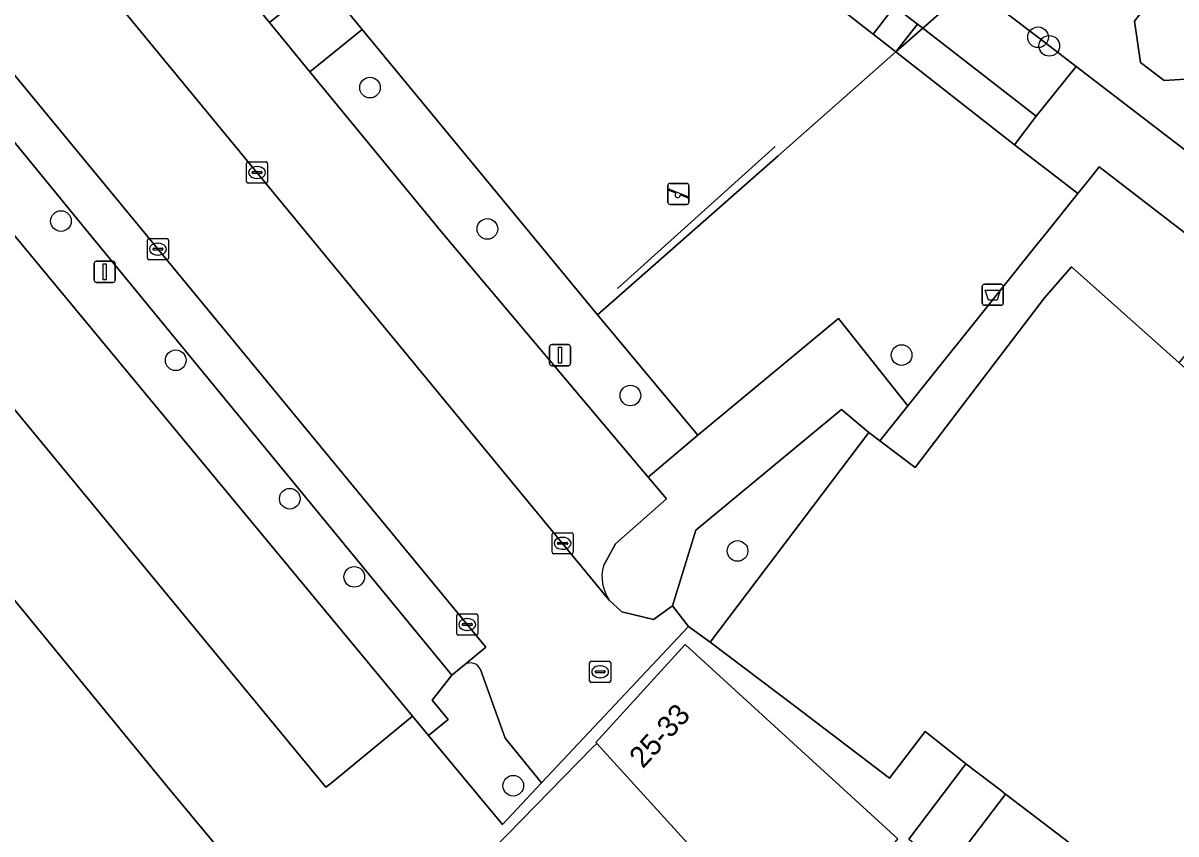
# Model space of a CAD drawing. Extents: x 160663 to 161506, y 382245 to 383291.
# Drawn here: x 160951.6 to 161006.2, y 382971.5 to 383010 of the extents above; entities that cross this region are included whole.
import ezdxf

# ---------------------------------------------------------------- set-up
doc = ezdxf.new("R2010")
doc.units = 0
for name, color, linetype in [('IMGEO_Afvalbak', 7, 'Continuous'), ('IMGEO_Boom', 7, 'Continuous'), ('IMGEO_Erf', 7, 'Continuous'), ('IMGEO_Groenvoorziening', 7, 'Continuous'), ('IMGEO_Hek', 7, 'Continuous'), ('IMGEO_Kolk', 7, 'Continuous'), ('IMGEO_Lichtmast', 7, 'Continuous'), ('IMGEO_Pand', 7, 'Continuous'), ('IMGEO_Pand_nummerreeks', 7, 'Continuous'), ('IMGEO_Parkeervlak_open', 7, 'Continuous'), ('IMGEO_Rijbaan_lokaal_open', 7, 'Continuous'), ('IMGEO_Rioolput', 7, 'Continuous'), ('IMGEO_Speelvoorziening', 7, 'Continuous'), ('IMGEO_Voetpad_halfverhard', 7, 'Continuous'), ('IMGEO_Voetpad_open', 7, 'Continuous')]:
    doc.layers.add(name, color=color, linetype=linetype)

msp = doc.modelspace()

# ---------------------------------------------------------------- linework, layer by layer
at = {"layer": 'IMGEO_Afvalbak'}
for p, q in [((160997.055, 382996.679), (160997.055, 382997.479)), ((160997.055, 382997.479), (160997.055, 382996.679)), ((160997.155, 382997.579), (160997.945, 382997.579)), ((160997.945, 382997.579), (160997.155, 382997.579)), ((160998.045, 382997.479), (160998.045, 382996.679)), ((160998.045, 382996.679), (160998.045, 382997.479)), ((160997.945, 382996.579), (160997.155, 382996.579)), ((160997.155, 382996.579), (160997.945, 382996.579))]:
    msp.add_line(p, q, dxfattribs=at)
msp.add_lwpolyline([(160997.198, 382997.293), (160997.902, 382997.293), (160997.753, 382996.823), (160997.347, 382996.823), (160997.198, 382997.293)], dxfattribs=at)
for centre, start, end in [((160997.155, 382997.479), 90, 180), ((160997.155, 382997.479), 90, 180), ((160997.945, 382997.479), 0, 90), ((160997.945, 382997.479), 360, 90), ((160997.155, 382996.679), 180, 270), ((160997.155, 382996.679), 180, 270), ((160997.945, 382996.679), 270, 0), ((160997.945, 382996.679), 270, 0)]:
    msp.add_arc(centre, 0.1, start, end, dxfattribs=at)
at = {"layer": 'IMGEO_Boom'}
for centre in [(160999.696, 383009.28), (161000.229, 383008.871), (160968.033, 383006.893), (160953.387, 383000.571), (160973.596, 383000.198), (160958.826, 382993.974), (160993.229, 382994.221), (160980.376, 382992.305), (160964.233, 382987.416), (160985.453, 382984.939), (160967.287, 382983.713), (160974.824, 382973.818)]:
    msp.add_circle(centre, 0.489, dxfattribs=at)
at = {"layer": 'IMGEO_Erf'}
for points in [[(160996.515, 383011.718), (161000, 383009.047), (161001.496, 383007.901), (161011.804, 383000), (161024.693, 382990.287), (161032.566, 383000), (161032.638, 383000.108), (161033.349, 383000.985), (161035.309, 383003.404), (161034.299, 383004.235), (161034.173, 383006.162), (161035.066, 383007.264), (161033.307, 383008.711), (161032.628, 383007.886), (161028.208, 383011.521)], [(160936.91, 383000), (160958.423, 382973.784), (160961.617, 382969.937)], [(160993.565, 382971.284), (160996.082, 382974.605), (160996.272, 382974.854), (160996.094, 382974.99), (160994.341, 382976.392), (160992.662, 382974.178), (160988.149, 382977.597), (160984.163, 382980.616), (160983.135, 382981.366), (160976.17, 382973.953), (160974.309, 382971.972), (160970.812, 382976.19), (160970.046, 382977.114), (160966.186, 382973.937), (160965.948, 382973.741), (160944.278, 383000)], [(160973.196, 382970.113), (160978.583, 382975.62), (160978.78, 382975.821), (160978.741, 382975.864), (160982.974, 382980.502), (160993.051, 382971.304)], [(161001.199, 382971.092), (161000, 382972.012), (160998.15, 382973.423), (160995.446, 382969.858)]]:
    msp.add_lwpolyline(points, dxfattribs=at)
for points in [[(161004.266, 383010.049), (161005.355, 383011.463), (161005.675, 383011.484), (161007.123, 383011.574), (161008.38, 383010.504), (161008.62, 383008.85), (161007.455, 383007.339), (161005.669, 383007.226), (161004.551, 383008.078)], [(161000, 382996.936), (161001.288, 382998.396), (161006.384, 382993.846), (161009.678, 382997.924), (161008.031, 382998.962), (161002.601, 383003.14), (161002.198, 383002.638), (161001.583, 383001.871), (161000.083, 383000), (161000, 382999.896), (160999.531, 382999.311), (160998.088, 382997.51), (160993.52, 382991.81), (160992.195, 382990.157), (160993.87, 382988.888)]]:
    msp.add_lwpolyline(points, close=True, dxfattribs=at)
at = {"layer": 'IMGEO_Groenvoorziening'}
for points in [[(160965.611, 383031.867), (160992.9, 383010.739), (160993.983, 383009.901), (160994.233, 383009.708), (160996.515, 383011.718), (160973.741, 383029.173), (160973.09, 383029.971), (160971.555, 383028.72), (160969.249, 383031.55), (160969.738, 383031.948), (160966.352, 383035.958)], [(160972.508, 382979.547), (160972.18, 382979.276), (160971.917, 382979.059), (160970.973, 382977.877), (160971.736, 382976.951), (160970.812, 382976.19), (160974.309, 382971.972), (160976.17, 382973.953), (160974.444, 382976.07)], [(160974.444, 382976.07), (160973.267, 382979.32)]]:
    msp.add_lwpolyline(points, dxfattribs=at)
for points in [[(160991.875, 383009.425), (160973.235, 383023.964), (160962.993, 383015.315), (160965.743, 383011.982), (160967.663, 383009.654), (160975.628, 383000), (160978.82, 382996.131), (160987.376, 383003.668), (160992.955, 383008.582)], [(161001.496, 383007.901), (161000, 383009.047), (160996.515, 383011.718), (160994.233, 383009.708), (160999.613, 383005.542), (161000, 383006.027)], [(160975.628, 383000), (160967.663, 383009.654), (160965.188, 383007.644), (160971.467, 383000), (160981.225, 382988.433), (160983.579, 382990.419), (160978.82, 382996.131)], [(160999.531, 382999.311), (161000, 382999.896), (161000.083, 383000), (161001.583, 383001.871), (161000.396, 383002.789), (161000, 383003.096), (160998.586, 383004.19), (160992.955, 383008.582), (160987.376, 383003.668), (160978.82, 382996.131), (160983.579, 382990.419), (160990.231, 382995.961), (160993.52, 382991.81), (160998.088, 382997.51)], [(160984.163, 382980.616), (160991.683, 382990.545), (160990.38, 382991.644), (160983.481, 382985.923), (160982.365, 382982.335), (160983.135, 382981.366)]]:
    msp.add_lwpolyline(points, close=True, dxfattribs=at)
msp.add_arc((160972.794, 382979.12), 0.514, 22.9356, 123.7629, dxfattribs=at)
at = {"layer": 'IMGEO_Hek'}
for points in [[(160951.771, 383023.978), (160963.274, 383009.974), (160965.743, 383011.982), (160967.663, 383009.654), (160978.82, 382996.131)], [(160994.233, 383009.708), (160996.515, 383011.718)], [(160992.955, 383008.582), (160994.233, 383009.708)], [(160979.758, 382997.374), (160987.235, 383004.108)]]:
    msp.add_lwpolyline(points, dxfattribs=at)
at = {"layer": 'IMGEO_Kolk'}
for p, q in [((160962.18, 383002.445), (160962.18, 383003.297)), ((160962.255, 383003.371), (160963.107, 383003.371)), ((160963.181, 383003.297), (160963.181, 383002.445)), ((160962.439, 383002.865), (160962.439, 383002.877)), ((160962.877, 383002.828), (160962.479, 383002.828)), ((160962.482, 383002.914), (160962.88, 383002.914)), ((160962.668, 383003.151), (160962.693, 383003.151)), ((160962.923, 383002.877), (160962.923, 383002.865)), ((160963.107, 383002.371), (160962.255, 383002.371)), ((160962.691, 383002.591), (160962.666, 383002.591)), ((160957.481, 382998.814), (160957.481, 382999.666)), ((160957.556, 382999.74), (160958.408, 382999.74)), ((160957.969, 382999.52), (160957.994, 382999.52)), ((160958.482, 382999.666), (160958.482, 382998.814)), ((160957.74, 382999.234), (160957.74, 382999.246)), ((160958.178, 382999.197), (160957.78, 382999.197)), ((160957.783, 382999.283), (160958.181, 382999.283)), ((160957.992, 382998.96), (160957.967, 382998.96)), ((160958.224, 382999.246), (160958.224, 382999.234)), ((160958.408, 382998.74), (160957.556, 382998.74)), ((160976.662, 382984.876), (160976.662, 382985.728)), ((160976.737, 382985.802), (160977.589, 382985.802)), ((160977.663, 382985.728), (160977.663, 382984.876)), ((160976.921, 382985.296), (160976.921, 382985.308)), ((160977.359, 382985.259), (160976.961, 382985.259)), ((160976.964, 382985.345), (160977.362, 382985.345)), ((160977.15, 382985.582), (160977.175, 382985.582)), ((160977.405, 382985.308), (160977.405, 382985.296)), ((160977.589, 382984.802), (160976.737, 382984.802)), ((160977.173, 382985.022), (160977.148, 382985.022)), ((160972.142, 382981.03), (160972.142, 382981.882)), ((160972.217, 382981.956), (160973.069, 382981.956)), ((160973.143, 382981.882), (160973.143, 382981.03)), ((160972.401, 382981.45), (160972.401, 382981.462)), ((160972.839, 382981.413), (160972.441, 382981.413)), ((160972.444, 382981.499), (160972.842, 382981.499)), ((160972.63, 382981.736), (160972.655, 382981.736)), ((160972.885, 382981.462), (160972.885, 382981.45)), ((160973.069, 382980.956), (160972.217, 382980.956)), ((160972.653, 382981.176), (160972.628, 382981.176))]:
    msp.add_line(p, q, dxfattribs=at)
for points in [[(160962.18, 383002.445), (160962.18, 383003.297)], [(160962.255, 383003.371), (160963.107, 383003.371)], [(160963.181, 383003.297), (160963.181, 383002.445)], [(160963.107, 383002.371), (160962.255, 383002.371)], [(160957.481, 382998.814), (160957.481, 382999.666)], [(160957.556, 382999.74), (160958.408, 382999.74)], [(160958.482, 382999.666), (160958.482, 382998.814)], [(160958.408, 382998.74), (160957.556, 382998.74)], [(160976.662, 382984.876), (160976.662, 382985.728)], [(160976.737, 382985.802), (160977.589, 382985.802)], [(160977.663, 382985.728), (160977.663, 382984.876)], [(160977.589, 382984.802), (160976.737, 382984.802)], [(160972.142, 382981.03), (160972.142, 382981.882)], [(160972.217, 382981.956), (160973.069, 382981.956)], [(160973.143, 382981.882), (160973.143, 382981.03)], [(160973.069, 382980.956), (160972.217, 382980.956)]]:
    msp.add_lwpolyline(points, dxfattribs=at)
for centre, radius, start, end in [((160962.257, 383003.295), 0.0765, 91.552, 178.448), ((160962.257, 383003.295), 0.0765, 91.552, 178.448), ((160963.105, 383003.295), 0.0765, 1.552, 88.448), ((160963.105, 383003.295), 0.0765, 1.552, 88.448), ((160962.479, 383002.874), 0.0403, 85.8775, 175.7526), ((160962.476, 383002.864), 0.0366, 178.938, 274.7102), ((160962.88, 383002.871), 0.043, 264.8664, 352.4533), ((160962.884, 383002.876), 0.0386, 1.7309, 96.639), ((160962.257, 383002.447), 0.0765, 181.552, 268.448), ((160962.257, 383002.447), 0.0765, 181.552, 268.448), ((160963.105, 383002.447), 0.0765, 271.552, 358.448), ((160963.105, 383002.447), 0.0765, 271.552, 358.448), ((160957.558, 382999.664), 0.0765, 91.552, 178.448), ((160957.558, 382999.664), 0.0765, 91.552, 178.448), ((160958.406, 382999.664), 0.0765, 1.552, 88.448), ((160958.406, 382999.664), 0.0765, 1.552, 88.448), ((160957.558, 382998.816), 0.0765, 181.552, 268.448), ((160957.558, 382998.816), 0.0765, 181.552, 268.448), ((160957.78, 382999.243), 0.0403, 85.8775, 175.7526), ((160957.777, 382999.233), 0.0366, 178.938, 274.7102), ((160958.181, 382999.24), 0.043, 264.8664, 352.4533), ((160958.185, 382999.245), 0.0386, 1.7309, 96.639), ((160958.406, 382998.816), 0.0765, 271.552, 358.448), ((160958.406, 382998.816), 0.0765, 271.552, 358.448), ((160976.739, 382985.726), 0.0765, 91.552, 178.448), ((160976.739, 382985.726), 0.0765, 91.552, 178.448), ((160977.587, 382985.726), 0.0765, 1.552, 88.448), ((160977.587, 382985.726), 0.0765, 1.552, 88.448), ((160976.961, 382985.305), 0.0403, 85.8775, 175.7526), ((160976.958, 382985.295), 0.0366, 178.938, 274.7102), ((160977.362, 382985.302), 0.043, 264.8664, 352.4533), ((160977.366, 382985.307), 0.0386, 1.7309, 96.639), ((160976.739, 382984.878), 0.0765, 181.552, 268.448), ((160976.739, 382984.878), 0.0765, 181.552, 268.448), ((160977.587, 382984.878), 0.0765, 271.552, 358.448), ((160977.587, 382984.878), 0.0765, 271.552, 358.448), ((160972.219, 382981.88), 0.0765, 91.552, 178.448), ((160972.219, 382981.88), 0.0765, 91.552, 178.448), ((160973.067, 382981.88), 0.0765, 1.552, 88.448), ((160973.067, 382981.88), 0.0765, 1.552, 88.448), ((160972.441, 382981.459), 0.0403, 85.8775, 175.7526), ((160972.438, 382981.449), 0.0366, 178.938, 274.7102), ((160972.842, 382981.456), 0.043, 264.8664, 352.4533), ((160972.846, 382981.461), 0.0386, 1.7309, 96.639), ((160972.219, 382981.032), 0.0765, 181.552, 268.448), ((160972.219, 382981.032), 0.0765, 181.552, 268.448), ((160973.067, 382981.032), 0.0765, 271.552, 358.448), ((160973.067, 382981.032), 0.0765, 271.552, 358.448)]:
    msp.add_arc(centre, radius, start, end, dxfattribs=at)
for centre, major_axis, ratio, start_param, end_param in [((160962.667, 383002.871), (-0.387, 0.002), 0.722429, 4.712389, 7.853982), ((160962.692, 383002.871), (-0.39, 0.002), 0.717154, 1.570796, 4.712389), ((160957.968, 382999.24), (-0.387, 0.002), 0.722429, 4.712389, 7.853982), ((160957.993, 382999.24), (-0.39, 0.002), 0.717154, 1.570796, 4.712389), ((160977.149, 382985.302), (-0.387, 0.002), 0.722429, 4.712389, 7.853982), ((160977.174, 382985.302), (-0.39, 0.002), 0.717154, 1.570796, 4.712389), ((160972.629, 382981.456), (-0.387, 0.002), 0.722429, 4.712389, 7.853982), ((160972.654, 382981.456), (-0.39, 0.002), 0.717154, 1.570796, 4.712389)]:
    msp.add_ellipse(centre, major_axis=major_axis, ratio=ratio, start_param=start_param, end_param=end_param, dxfattribs=at)
at = {"layer": 'IMGEO_Lichtmast'}
for p, q in [((160954.961, 382997.766), (160954.961, 382998.566)), ((160954.961, 382998.566), (160954.961, 382997.766)), ((160955.061, 382998.666), (160955.851, 382998.666)), ((160955.851, 382998.666), (160955.061, 382998.666)), ((160955.951, 382998.566), (160955.951, 382997.766)), ((160955.951, 382997.766), (160955.951, 382998.566)), ((160955.851, 382997.666), (160955.061, 382997.666)), ((160955.061, 382997.666), (160955.851, 382997.666)), ((160976.546, 382993.815), (160976.546, 382994.615)), ((160976.546, 382994.615), (160976.546, 382993.815)), ((160976.646, 382994.715), (160977.436, 382994.715)), ((160977.436, 382994.715), (160976.646, 382994.715)), ((160977.536, 382994.615), (160977.536, 382993.815)), ((160977.536, 382993.815), (160977.536, 382994.615)), ((160977.436, 382993.715), (160976.646, 382993.715)), ((160976.646, 382993.715), (160977.436, 382993.715))]:
    msp.add_line(p, q, dxfattribs=at)
for points in [[(160955.381, 382998.541), (160955.531, 382998.541), (160955.531, 382997.791), (160955.381, 382997.791), (160955.381, 382998.541)], [(160976.966, 382994.59), (160977.116, 382994.59), (160977.116, 382993.84), (160976.966, 382993.84), (160976.966, 382994.59)]]:
    msp.add_lwpolyline(points, dxfattribs=at)
for centre, start, end in [((160955.061, 382998.566), 90, 180), ((160955.061, 382998.566), 90, 180), ((160955.851, 382998.566), 0, 90), ((160955.851, 382998.566), 360, 90), ((160955.061, 382997.766), 180, 270), ((160955.061, 382997.766), 180, 270), ((160955.851, 382997.766), 270, 0), ((160955.851, 382997.766), 270, 0), ((160976.646, 382994.615), 90, 180), ((160976.646, 382994.615), 90, 180), ((160977.436, 382994.615), 0, 90), ((160977.436, 382994.615), 360, 90), ((160976.646, 382993.815), 180, 270), ((160976.646, 382993.815), 180, 270), ((160977.436, 382993.815), 270, 0), ((160977.436, 382993.815), 270, 0)]:
    msp.add_arc(centre, 0.1, start, end, dxfattribs=at)
at = {"layer": 'IMGEO_Pand'}
for points in [[(160970.046, 382977.114), (160951.094, 383000), (160937.187, 383016.894), (160933.327, 383013.717), (160933.107, 383013.536), (160944.278, 383000), (160965.948, 382973.741), (160966.186, 382973.937)], [(160936.91, 383000), (160925.377, 383014.054), (160925.308, 383014.138), (160917.332, 383007.56), (160917.629, 383007.213), (160923.54, 383000), (160953.589, 382963.329), (160961.617, 382969.937), (160958.423, 382973.784)], [(161004.266, 383010.049), (161004.551, 383008.078), (161005.669, 383007.226), (161007.455, 383007.339), (161008.62, 383008.85), (161008.38, 383010.504), (161007.123, 383011.574), (161005.675, 383011.484), (161005.355, 383011.463)], [(161021.889, 382983.539), (161021.424, 382982.963), (161020.229, 382981.484), (161010.392, 382990.267), (161006.384, 382993.846), (161001.288, 382998.396), (161000, 382996.936), (160993.87, 382988.888), (160992.195, 382990.157), (160991.683, 382990.545), (160984.163, 382980.616), (160988.149, 382977.597), (160992.662, 382974.178), (160994.341, 382976.392), (160996.094, 382974.99), (160996.272, 382974.854), (160997.96, 382973.567), (160998.081, 382973.475), (160998.15, 382973.423), (161000, 382972.012), (161001.199, 382971.092), (161002.915, 382969.775), (161015.758, 382959.65), (161029.997, 382977.303)], [(160982.974, 382980.502), (160978.741, 382975.864), (160978.78, 382975.821), (160988.34, 382965.314), (160993.051, 382971.304)], [(160978.78, 382975.821), (160978.583, 382975.62), (160973.196, 382970.113), (160978.517, 382965.213), (160977.888, 382964.488), (160983.601, 382959.296), (160983.622, 382959.281), (160984.019, 382959.789), (160988.236, 382965.181), (160988.34, 382965.314)], [(160998.15, 382973.423), (160998.081, 382973.475), (160997.96, 382973.567), (160996.272, 382974.854), (160996.082, 382974.605), (160993.565, 382971.284), (160995.111, 382970.112), (160995.377, 382969.91), (160995.446, 382969.858)]]:
    msp.add_lwpolyline(points, close=True, dxfattribs=at)
at = {"layer": 'IMGEO_Parkeervlak_open'}
for points in [[(160965.188, 383007.644), (160963.274, 383009.974), (160951.771, 383023.978), (160947.904, 383020.802), (160965.045, 383000), (160979.376, 382982.615)], [(160938.803, 383018.726), (160941.068, 383016.598), (160942.148, 383015.356), (160954.712, 383000), (160965.713, 382986.582), (160971.917, 382979.059), (160972.18, 382979.276), (160972.508, 382979.547), (160973.527, 382980.386), (160957.356, 383000), (160944.076, 383016.107)], [(160979.095, 382984.232), (160979.664, 382985.281), (160982.084, 382987.414), (160981.225, 382988.433), (160971.467, 383000), (160965.188, 383007.644)]]:
    msp.add_lwpolyline(points, dxfattribs=at)
msp.add_arc((160980.966, 382983.724), 1.939, 164.8162, 214.9004, dxfattribs=at)
at = {"layer": 'IMGEO_Rijbaan_lokaal_open'}
for points in [[(160944.793, 383020.424), (160941.074, 383023.981), (160920.302, 383043.863), (160917.937, 383041.481), (160918.109, 383041.314), (160931.492, 383028.374), (160941.045, 383019.344), (160942.976, 383017.415), (160944.076, 383016.107), (160957.356, 383000), (160973.527, 382980.386), (160972.508, 382979.547)], [(160973.267, 382979.32), (160974.444, 382976.07), (160976.17, 382973.953), (160983.135, 382981.366), (160982.365, 382982.335), (160981.47, 382981.695), (160979.968, 382982.054), (160979.376, 382982.615), (160965.045, 383000), (160947.904, 383020.802)]]:
    msp.add_lwpolyline(points, dxfattribs=at)
msp.add_arc((160972.794, 382979.12), 0.514, 22.9356, 123.7629, dxfattribs=at)
at = {"layer": 'IMGEO_Rioolput'}
for p, q in [((160978.517, 382979.715), (160979.369, 382979.715)), ((160978.442, 382978.789), (160978.442, 382979.641)), ((160978.701, 382979.209), (160978.701, 382979.221)), ((160979.139, 382979.172), (160978.741, 382979.172)), ((160978.744, 382979.258), (160979.142, 382979.258)), ((160978.93, 382979.495), (160978.955, 382979.495)), ((160979.185, 382979.221), (160979.185, 382979.209)), ((160979.443, 382979.641), (160979.443, 382978.789)), ((160979.369, 382978.715), (160978.517, 382978.715)), ((160978.953, 382978.935), (160978.928, 382978.935))]:
    msp.add_line(p, q, dxfattribs=at)
for points in [[(160978.517, 382979.715), (160979.369, 382979.715)], [(160978.442, 382978.789), (160978.442, 382979.641)], [(160979.443, 382979.641), (160979.443, 382978.789)], [(160979.369, 382978.715), (160978.517, 382978.715)]]:
    msp.add_lwpolyline(points, dxfattribs=at)
for centre, radius, start, end in [((160978.519, 382979.639), 0.0765, 91.552, 178.448), ((160978.519, 382979.639), 0.0765, 91.552, 178.448), ((160979.367, 382979.639), 0.0765, 1.552, 88.448), ((160979.367, 382979.639), 0.0765, 1.552, 88.448), ((160978.741, 382979.218), 0.0403, 85.8775, 175.7526), ((160978.738, 382979.208), 0.0366, 178.938, 274.7102), ((160979.142, 382979.215), 0.043, 264.8664, 352.4533), ((160979.146, 382979.22), 0.0386, 1.7309, 96.639), ((160978.519, 382978.791), 0.0765, 181.552, 268.448), ((160978.519, 382978.791), 0.0765, 181.552, 268.448), ((160979.367, 382978.791), 0.0765, 271.552, 358.448), ((160979.367, 382978.791), 0.0765, 271.552, 358.448)]:
    msp.add_arc(centre, radius, start, end, dxfattribs=at)
for centre, major_axis, ratio, start_param, end_param in [((160978.929, 382979.215), (-0.387, 0.002), 0.722429, 4.712389, 7.853982), ((160978.954, 382979.215), (-0.39, 0.002), 0.717154, 1.570796, 4.712389)]:
    msp.add_ellipse(centre, major_axis=major_axis, ratio=ratio, start_param=start_param, end_param=end_param, dxfattribs=at)
at = {"layer": 'IMGEO_Speelvoorziening'}
for p, q in [((160982.154, 383001.457), (160982.154, 383002.257)), ((160982.154, 383002.257), (160982.154, 383001.457)), ((160982.254, 383002.357), (160983.044, 383002.357)), ((160983.044, 383002.357), (160982.254, 383002.357)), ((160983.144, 383002.257), (160983.144, 383001.457)), ((160983.144, 383001.457), (160983.144, 383002.257)), ((160982.537, 383001.885), (160982.198, 383002.022)), ((160982.223, 383002.082), (160983.099, 383001.729)), ((160983.075, 383001.669), (160982.735, 383001.806)), ((160983.044, 383001.357), (160982.254, 383001.357)), ((160982.254, 383001.357), (160983.044, 383001.357))]:
    msp.add_line(p, q, dxfattribs=at)
for centre, radius, start, end in [((160982.254, 383002.257), 0.1, 90, 180), ((160982.254, 383002.257), 0.1, 90, 180), ((160982.211, 383002.052), 0.0327, 68.078, 248.078), ((160983.044, 383002.257), 0.1, 0, 90), ((160983.044, 383002.257), 0.1, 360, 90), ((160982.616, 383001.795), 0.12, 130.9928, 5.1632), ((160983.087, 383001.699), 0.0327, 248.078, 68.078), ((160982.254, 383001.457), 0.1, 180, 270), ((160982.254, 383001.457), 0.1, 180, 270), ((160983.044, 383001.457), 0.1, 270, 0), ((160983.044, 383001.457), 0.1, 270, 0)]:
    msp.add_arc(centre, radius, start, end, dxfattribs=at)
at = {"layer": 'IMGEO_Voetpad_halfverhard'}
msp.add_lwpolyline([(160955.126, 383026.948), (160954.085, 383026.085), (160957.797, 383021.6), (160962.413, 383025.421), (160966.287, 383028.692), (160966.717, 383029.048), (160973.235, 383023.964), (160991.875, 383009.425), (160992.9, 383010.739), (160965.611, 383031.867), (160958.925, 383026.141), (160954.207, 383028.3), (160954.088, 383028.201)], close=True, dxfattribs=at)
at = {"layer": 'IMGEO_Voetpad_open'}
for points in [[(160917.623, 383041.165), (160916.299, 383039.832), (160916.51, 383039.63), (160928.616, 383028.044), (160931.868, 383024.973), (160937.287, 383019.841), (160935.954, 383018.87), (160937.187, 383016.894), (160951.094, 383000), (160970.046, 382977.114), (160970.812, 382976.19), (160971.736, 382976.951), (160970.973, 382977.877), (160971.917, 382979.059), (160965.713, 382986.582), (160954.712, 383000), (160942.148, 383015.356), (160941.068, 383016.598), (160938.803, 383018.726)], [(160983.481, 382985.923), (160990.38, 382991.644), (160991.683, 382990.545), (160992.195, 382990.157), (160993.52, 382991.81), (160990.231, 382995.961), (160983.579, 382990.419), (160981.225, 382988.433), (160982.084, 382987.414), (160979.664, 382985.281), (160979.095, 382984.232)], [(160979.376, 382982.615), (160979.968, 382982.054), (160981.47, 382981.695), (160982.365, 382982.335), (160983.481, 382985.923)]]:
    msp.add_lwpolyline(points, dxfattribs=at)
for points in [[(160965.188, 383007.644), (160967.663, 383009.654), (160965.743, 383011.982), (160963.274, 383009.974)], [(160993.983, 383009.901), (160992.9, 383010.739), (160991.875, 383009.425), (160992.955, 383008.582)], [(160992.955, 383008.582), (160994.233, 383009.708), (160993.983, 383009.901)], [(160992.955, 383008.582), (160998.586, 383004.19), (160999.613, 383005.542), (160994.233, 383009.708)], [(161011.804, 383000), (161001.496, 383007.901), (161000, 383006.027), (160999.613, 383005.542), (160998.586, 383004.19), (161000, 383003.096), (161000.396, 383002.789), (161001.583, 383001.871), (161002.198, 383002.638), (161002.601, 383003.14), (161008.031, 382998.962), (161009.678, 382997.924), (161013.992, 382994.722), (161016.538, 382993.373), (161028.645, 382983.591), (161032.535, 382980.449), (161033.994, 382982.407), (161034.101, 382982.551), (161030.239, 382985.727), (161024.693, 382990.287)]]:
    msp.add_lwpolyline(points, close=True, dxfattribs=at)
msp.add_arc((160980.966, 382983.724), 1.939, 164.8162, 214.9004, dxfattribs=at)

# ---------------------------------------------------------------- texts
at = {"layer": 'IMGEO_Pand_nummerreeks'}
msp.add_text('25-33', height=1, rotation=47.6128, dxfattribs=at).set_placement((160980.967, 382974.596))

doc.saveas('drawing.dxf')
